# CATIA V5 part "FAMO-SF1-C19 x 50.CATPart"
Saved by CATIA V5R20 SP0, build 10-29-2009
Part number: FAMO-SF1-C19 x 50
Definition: NONE
Nomenclature: FAMO-SF1-C19 x 50
Source: Unknown
Description: FAMO-SF1-C19 x 50
Bounding box of the stored display mesh (mm): x -32 to 18, y -17 to 17, z -17 to 17
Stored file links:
  C:\Users\Utente\Desktop\IO LAVORO\3D X SITO CF\X SITO\FAMO\FAMO-SF1-C19 x 50.CATPart
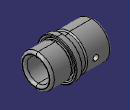
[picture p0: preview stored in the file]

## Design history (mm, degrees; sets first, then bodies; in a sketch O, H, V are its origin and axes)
Body1 "FAMO-SF1-C19 x 50" (main body)
  Solid1: solid without history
